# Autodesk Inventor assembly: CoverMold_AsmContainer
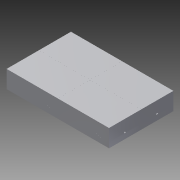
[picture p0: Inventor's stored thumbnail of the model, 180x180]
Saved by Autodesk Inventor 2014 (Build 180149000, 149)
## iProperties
Created: 2009-12
Part Number: CoverMold_AsmContainer
Document SubType Name: Assembly
Designer: gaom
Author: gaom
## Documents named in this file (9)
- C:\Users\iTools\Desktop\tutorial files\Mold\CoverMold\Cover Mold\CoverMold_AsmContainer.iam
- C:\Users\iTools\Desktop\tutorial files\Mold\CoverMold\Cover Mold\CoverMold_cover_CR_1.ipt
- C:\Users\iTools\Desktop\tutorial files\Mold\CoverMold\Cover Mold\CoverMold_cover_CV_1.ipt
- C:\Users\iTools\Desktop\tutorial files\Mold\CoverMold\Cover Mold\CoverMold_cover_CR_2.ipt
- C:\Users\iTools\Desktop\tutorial files\Mold\CoverMold\Cover Mold\CoverMold_cover_CV_2.ipt
- C:\Users\iTools\Desktop\tutorial files\Mold\CoverMold\Cover Mold\CoverMold_cover_CR_3.ipt
- C:\Users\iTools\Desktop\tutorial files\Mold\CoverMold\Cover Mold\CoverMold_cover_CV_3.ipt
- C:\Users\iTools\Desktop\tutorial files\Mold\CoverMold\Cover Mold\CoverMold_cover_CR_4.ipt
- C:\Users\iTools\Desktop\tutorial files\Mold\CoverMold\Cover Mold\CoverMold_cover_CV_4.ipt
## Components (8 placed, 8 different names)
1. CoverMold_cover_CR_1:1
2. CoverMold_cover_CV_1:1
3. CoverMold_cover_CR_2:1
4. CoverMold_cover_CV_2:1
5. CoverMold_cover_CR_3:1
6. CoverMold_cover_CV_3:1
7. CoverMold_cover_CR_4:1
8. CoverMold_cover_CV_4:1
